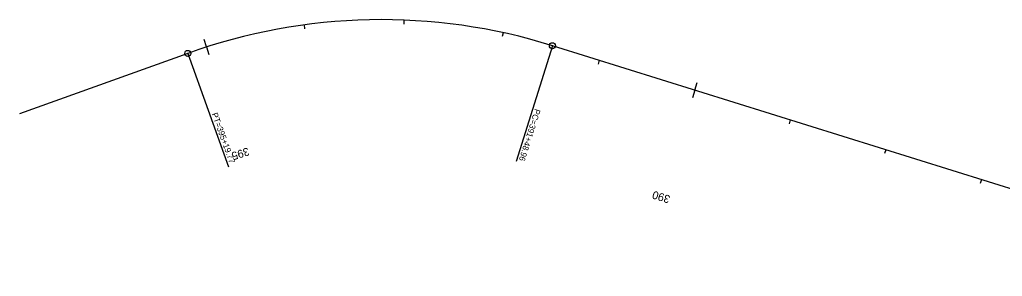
# Model space of a CAD drawing. Extents: x 144 to 1452322, y 4017 to 1128039.
# Drawn here: x 1448763 to 1449745, y 1126676 to 1126933 of the extents above; entities that cross this region are included whole.
import ezdxf

# ---------------------------------------------------------------- set-up
doc = ezdxf.new("R2010")
doc.units = 0
for name, color, linetype in [('RD_HC_Cl', 7, 'Continuous'), ('RD_HC_Data', 7, 'Continuous'), ('RD_HC_Data_Tic', 7, 'Continuous'), ('RD_HC_TX_Sta50', 7, 'Continuous'), ('RD_SMD_Locator', 7, 'Continuous')]:
    doc.layers.add(name, color=color, linetype=linetype)

msp = doc.modelspace()

# ---------------------------------------------------------------- linework, layer by layer
at = {"layer": 'RD_HC_Cl'}
for p, q in [((1448931, 1126898.83), (1448763.03, 1126838.55)), ((1450033.34, 1126676.03), (1449295.29, 1126906.46))]:
    msp.add_line(p, q, dxfattribs=at)
msp.add_arc((1449124.53, 1126359.54), 572.96, 72.66042, 109.74133, dxfattribs=at)
at = {"layer": 'RD_HC_Data'}
for p, q in [((1448931, 1126898.83), (1448971.66, 1126785.54)), ((1449295.29, 1126906.46), (1449259.13, 1126790.64))]:
    msp.add_line(p, q, dxfattribs=at)
for centre, radius in [((1449295.29, 1126906.46), 3), ((1448931, 1126898.83), 3), ((1448931, 1126898.83), 0.282), ((1449295.29, 1126906.46), 0.282)]:
    msp.add_circle(centre, radius, dxfattribs=at)
at = {"layer": 'RD_HC_Data_Tic'}
for p, q in [((1449146.88, 1126932.07), (1449146.73, 1126928.07)), ((1449047.13, 1126927.25), (1449047.67, 1126923.29)), ((1449245.96, 1126919.49), (1449245.11, 1126915.58)), ((1448949.72, 1126905.18), (1448947.28, 1126912.8)), ((1448949.72, 1126905.18), (1448952.16, 1126897.56)), ((1449342.03, 1126891.87), (1449340.84, 1126888.05)), ((1449437.48, 1126862.07), (1449439.87, 1126869.7)), ((1449437.48, 1126862.07), (1449435.1, 1126854.43)), ((1449532.94, 1126832.26), (1449531.75, 1126828.45)), ((1449628.4, 1126802.46), (1449627.2, 1126798.64)), ((1449723.85, 1126772.66), (1449722.66, 1126768.84))]:
    msp.add_line(p, q, dxfattribs=at)
at = {"layer": 'RD_SMD_Locator'}
for centre in [(1448931, 1126898.83), (1449295.29, 1126906.46)]:
    msp.add_circle(centre, 0.15, dxfattribs=at)

# ---------------------------------------------------------------- texts
at = {"layer": 'RD_HC_Data'}
for s, rotation, p in [('PC=391+48.96', 252.66042, (1449277.83, 1126843.82)), ('PT=395+19.77', 289.74133, (1448954.84, 1126838.32))]:
    msp.add_text(s, height=6, rotation=rotation, dxfattribs=at).set_placement(p)
at = {"layer": 'RD_HC_TX_Sta50'}
for s, rotation, p in [('395', 197.76428, (1448990.96, 1126804.99)), ('390', 162.66042, (1449413.63, 1126756.37))]:
    msp.add_text(s, height=8, rotation=rotation, dxfattribs=at).set_placement(p)

doc.saveas('drawing.dxf')
